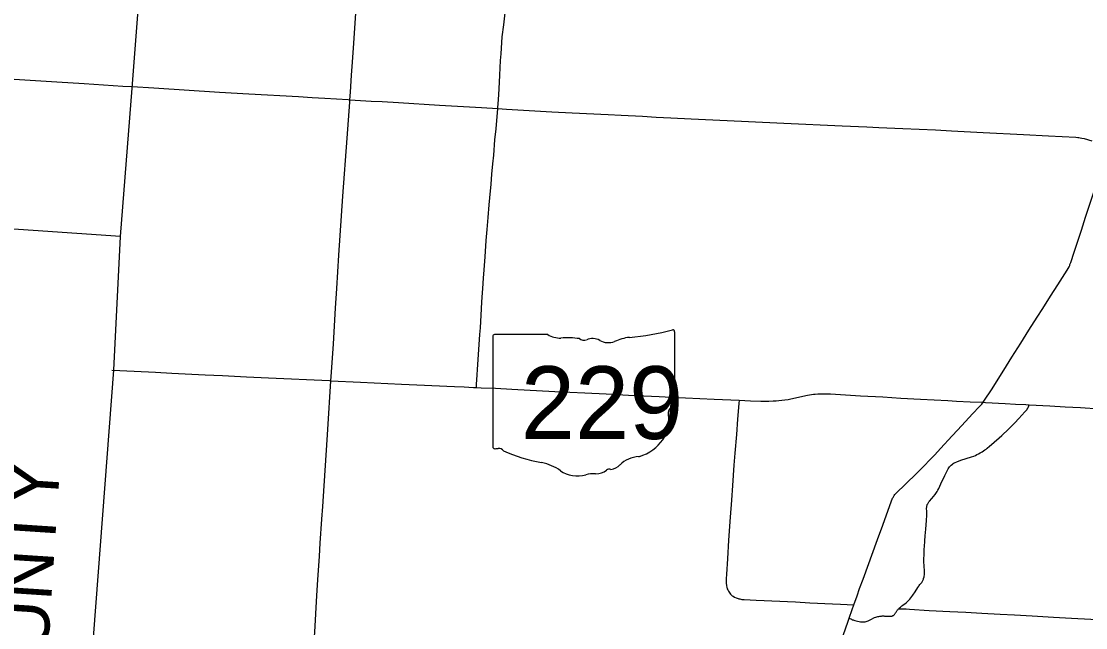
# Model space of a CAD drawing. Extents: x 9078 to 9739, y 4248 to 4966.
# Drawn here: x 9241.2 to 9343, y 4361.8 to 4419.9 of the extents above; entities that cross this region are included whole.
import ezdxf

# ---------------------------------------------------------------- set-up
doc = ezdxf.new("R2010")
doc.units = 0
for name, color, linetype in [('GM_X_Adjacent_County_Text', 7, 'Continuous'), ('GM_X_County', 7, 'Continuous'), ('GM_X_County_Road', 7, 'Continuous'), ('GM_X_State_Route', 7, 'Continuous'), ('GM_X_State_Shield', 7, 'Continuous'), ('GM_X_Township', 7, 'Continuous'), ('GM_X_Township_Road', 7, 'Continuous')]:
    doc.layers.add(name, color=color, linetype=linetype)

msp = doc.modelspace()

# ---------------------------------------------------------------- linework, layer by layer
at = {"layer": 'GM_X_County'}
msp.add_lwpolyline([(9453.47, 4282.4), (9434.47, 4283.67), (9411.76, 4284.99), (9398.2, 4285.94), (9380.71, 4287.14), (9368.35, 4287.79), (9345.5, 4289.28), (9319.89, 4290.94), (9309.14, 4291.62), (9253.07, 4295.4), (9243.76, 4295.73), (9243.93, 4298), (9244.32, 4304.05), (9245.53, 4321.55), (9248.17, 4361.29), (9250.08, 4386.45), (9250.73, 4399.27), (9229.79, 4400.68)], dxfattribs=at)
at = {"layer": 'GM_X_County_Road'}
for points in [[(9333.24, 4383.38), (9333.37, 4383.57), (9334.02, 4384.59), (9335.2, 4386.47), (9335.99, 4387.71), (9336.83, 4389.03), (9337.61, 4390.28), (9338.4, 4391.52), (9338.93, 4392.36), (9339.68, 4393.53), (9340.39, 4394.63), (9341.26, 4396.02), (9341.45, 4396.36), (9341.51, 4396.49), (9341.54, 4396.58), (9341.61, 4396.77), (9341.95, 4397.77), (9342.63, 4399.87), (9343.04, 4401.12), (9343.6, 4402.83), (9344.88, 4406.73), (9345.27, 4407.93)], [(9269.22, 4360.07), (9269.3, 4361.37), (9269.5, 4364.89), (9269.59, 4366.37), (9269.74, 4368.65), (9269.82, 4369.89), (9269.97, 4372.18), (9270.06, 4373.41), (9270.13, 4374.39), (9270.19, 4375.37), (9270.42, 4378.81), (9270.55, 4380.78), (9270.85, 4385.45)], [(9320.87, 4363.98), (9321.17, 4364.85), (9321.42, 4365.54), (9321.76, 4366.46), (9323.12, 4370.25), (9323.63, 4371.63), (9324.46, 4373.95), (9324.53, 4374.11), (9324.57, 4374.2), (9324.62, 4374.28), (9324.68, 4374.38), (9324.73, 4374.46), (9324.8, 4374.55), (9324.89, 4374.65), (9326.83, 4376.54), (9327.52, 4377.24), (9328.21, 4377.95), (9328.6, 4378.36), (9329.16, 4378.96), (9330.27, 4380.17), (9330.77, 4380.71), (9331.56, 4381.55), (9332.22, 4382.27), (9332.9, 4382.99), (9333.1, 4383.2), (9333.24, 4383.38)], [(9320.42, 4362.71), (9320.72, 4363.53), (9320.87, 4363.98)], [(9318.48, 4357.29), (9318.82, 4358.2), (9319.07, 4358.9), (9319.32, 4359.59), (9319.59, 4360.36), (9320.02, 4361.6), (9320.36, 4362.53), (9320.42, 4362.71)]]:
    msp.add_lwpolyline(points, dxfattribs=at)
at = {"layer": 'GM_X_State_Route'}
for points in [[(9249.89, 4386.47), (9250.64, 4386.43), (9254.08, 4386.26), (9255.64, 4386.18), (9258.83, 4386.01), (9260.47, 4385.94), (9262.76, 4385.83), (9264.89, 4385.73), (9270.71, 4385.46), (9270.85, 4385.45), (9273.66, 4385.32), (9277.59, 4385.13), (9279.07, 4385.06), (9282.67, 4384.89), (9283.6, 4384.85)], [(9283.6, 4384.85), (9284.47, 4384.81), (9284.76, 4384.79), (9285.21, 4384.77), (9286.6, 4384.72), (9288.16, 4384.64), (9292.26, 4384.43), (9295.12, 4384.28), (9297.17, 4384.18), (9299.3, 4384.07), (9302.25, 4383.93), (9303.4, 4383.87), (9307.49, 4383.69), (9309.89, 4383.58), (9310.98, 4383.53), (9311.98, 4383.49), (9312.36, 4383.5), (9312.72, 4383.5), (9313.16, 4383.52), (9313.43, 4383.53), (9313.7, 4383.56), (9313.98, 4383.58), (9314.27, 4383.61), (9314.58, 4383.66), (9314.84, 4383.71), (9316.44, 4384.05), (9317.01, 4384.15), (9317.17, 4384.17), (9317.41, 4384.19), (9317.6, 4384.2), (9317.9, 4384.2), (9318.64, 4384.18), (9321.51, 4384.01), (9323.63, 4383.89), (9325.35, 4383.79), (9327.24, 4383.68), (9328.55, 4383.62), (9329.86, 4383.55), (9330.68, 4383.5), (9331.99, 4383.44), (9333.24, 4383.38), (9333.46, 4383.37), (9335.34, 4383.27), (9336.33, 4383.21), (9337.31, 4383.16), (9337.62, 4383.14), (9339.6, 4383.04), (9341.07, 4382.95), (9342.55, 4382.87), (9344.35, 4382.77)]]:
    msp.add_lwpolyline(points, dxfattribs=at)
at = {"layer": 'GM_X_State_Shield'}
for p, q in [((9286.32, 4389.69), (9286.32, 4379.13)), ((9291.59, 4389.87), (9286.5, 4389.87)), ((9303.73, 4384.61), (9303.73, 4390.14)), ((9303.72, 4384.61), (9303.73, 4384.61))]:
    msp.add_line(p, q, dxfattribs=at)
for centre, major_axis, start_param, end_param in [((9297.53, 4404.28), (18.45, 0), 4.814394, 5.042369), ((9303.53, 4390.16), (0.194, 0), 6.141152, 7.989035), ((9286.52, 4389.71), (0.202, 0), 1.712693, 3.28349), ((9292.81, 4391.1), (1.96, 0), 4.042523, 4.731795), ((9293.45, 4383.94), (7.02, 0), 1.404758, 1.657858), ((9295.05, 4389.77), (0.564, 0), 3.836095, 5.185415), ((9295.88, 4388.55), (1.17, 0), 0.950623, 2.079405), ((9297.39, 4390.22), (1.41, 0), 4.081561, 5.145723), ((9299.88, 4386.65), (3.71, 0), 1.699011, 2.107814), ((9303.68, 4384.2), (0.3, 0), 1.883978, 3.671073), ((9303.52, 4384.59), (0.207, 0), 5.05454, 6.418171), ((9301.77, 4383.5), (1.8, 0), 5.934695, 6.695948), ((9298.56, 4381.59), (4.62, 0), 5.101752, 6.440018), ((9304.42, 4382.3), (1.31, 0), 2.387724, 3.262537), ((9286.53, 4379.1), (0.203, 0), 3.00124, 4.508301), ((9286.56, 4380.18), (1.55, 0), 4.665946, 4.897461), ((9286.87, 4378.52), (0.56, 0), 0.519207, 1.627899), ((9293.94, 4388.01), (13.33, 0), 4.195997, 4.488961), ((9300.51, 4376.16), (2.53, 0), 1.647645, 2.488434), ((9289.97, 4374.38), (4.17, 0), 0.823519, 1.323587), ((9297.3, 4378.1), (1.49, 0), 4.937069, 5.64225), ((9294.48, 4378.46), (2.65, 0), 4.026481, 4.996735), ((9296, 4374.81), (2.17, 0), 1.495662, 1.94098), ((9296.2, 4377.67), (1.41, 0), 4.691044, 5.507374), ((9297.47, 4376.65), (0.397, 0), 1.147584, 2.315152)]:
    msp.add_ellipse(centre, major_axis=major_axis, ratio=0.8, start_param=start_param, end_param=end_param, dxfattribs=at)
at = {"layer": 'GM_X_Township'}
msp.add_lwpolyline([(9250.73, 4399.27), (9251.82, 4413.47), (9252.62, 4423.86), (9252.83, 4426.7), (9268.7, 4425.69), (9274.03, 4425.41), (9274.32, 4425.46), (9274.89, 4425.45), (9288.03, 4424.54), (9349.47, 4420.87), (9376.69, 4419.12)], dxfattribs=at)
at = {"layer": 'GM_X_Township_Road'}
for points in [[(9286.81, 4411.51), (9286.82, 4411.61), (9286.87, 4412.34), (9286.93, 4413.4), (9287, 4414.71), (9287.08, 4416.11), (9287.12, 4416.76), (9287.19, 4417.82), (9287.24, 4418.39), (9287.37, 4419.53), (9287.52, 4420.67), (9287.63, 4421.48), (9287.83, 4422.86), (9288.01, 4423.91), (9288.13, 4424.61)], [(9272.82, 4414.69), (9272.87, 4415.55), (9272.98, 4416.86), (9273.03, 4417.76), (9273.25, 4421.11)], [(9231.64, 4414.87), (9232.85, 4414.81), (9233.83, 4414.74), (9234.9, 4414.68), (9236.12, 4414.6), (9237.11, 4414.53), (9240.54, 4414.32), (9244.64, 4414.07), (9247.25, 4413.9), (9250.94, 4413.66), (9251.85, 4413.61)], [(9272.67, 4412.35), (9272.72, 4413.09), (9272.82, 4414.69)], [(9251.85, 4413.61), (9253.9, 4413.48), (9260.2, 4413.09), (9262.98, 4412.93), (9267.73, 4412.65), (9269.04, 4412.57), (9270.27, 4412.5), (9272.48, 4412.36), (9272.67, 4412.35)], [(9270.85, 4385.45), (9270.9, 4386.27), (9271.08, 4388.97), (9271.29, 4392.41), (9271.41, 4394.29), (9271.6, 4397.48), (9271.73, 4399.36), (9271.99, 4403.12), (9272.4, 4408.68), (9272.66, 4412.11), (9272.67, 4412.35)], [(9272.67, 4412.35), (9274.69, 4412.22), (9275.75, 4412.17), (9277.31, 4412.09), (9281.24, 4411.84), (9285.25, 4411.6), (9286.81, 4411.51)], [(9284.76, 4384.79), (9284.76, 4384.94), (9284.77, 4385.11), (9284.79, 4385.52), (9284.89, 4386.99), (9284.96, 4387.97), (9285.09, 4389.86), (9285.14, 4390.51), (9285.22, 4391.74), (9285.28, 4392.97), (9285.32, 4393.46), (9285.38, 4394.28), (9285.45, 4395.26), (9285.51, 4396.08), (9285.57, 4396.9), (9285.6, 4397.31), (9285.71, 4398.86), (9285.79, 4399.92), (9285.88, 4401.07), (9285.99, 4402.3), (9286.04, 4402.95), (9286.16, 4404.26), (9286.25, 4405.24), (9286.34, 4406.22), (9286.42, 4407.04), (9286.54, 4408.51), (9286.64, 4409.57), (9286.81, 4411.51)], [(9286.81, 4411.51), (9287.63, 4411.46), (9291.97, 4411.2), (9293.93, 4411.1), (9297.37, 4410.93), (9298.6, 4410.87), (9300.65, 4410.77), (9301.96, 4410.69), (9303.35, 4410.61), (9305.32, 4410.51), (9307.38, 4410.42), (9310.78, 4410.26), (9314.16, 4410.1), (9319.74, 4409.85), (9322.11, 4409.75), (9323.26, 4409.71), (9325.55, 4409.6), (9328.67, 4409.46), (9330.22, 4409.39), (9333.25, 4409.22), (9337.1, 4409.02), (9339.48, 4408.89), (9342.1, 4408.76), (9342.28, 4408.74), (9342.4, 4408.73), (9342.51, 4408.72), (9342.67, 4408.68), (9342.91, 4408.63), (9343.62, 4408.43)], [(9309.89, 4383.58), (9309.86, 4383.26), (9309.75, 4381.78), (9309.63, 4380.31), (9309.47, 4378.51), (9309.39, 4377.37), (9309.25, 4375.41), (9309.15, 4374.02), (9309.04, 4372.39), (9308.89, 4370.18), (9308.78, 4368.39), (9308.68, 4366.91), (9308.66, 4366.48), (9308.65, 4366.35), (9308.65, 4366.14), (9308.66, 4366.01), (9308.67, 4365.92), (9308.69, 4365.81), (9308.71, 4365.68), (9308.76, 4365.53), (9308.81, 4365.42), (9308.87, 4365.3), (9309.01, 4365.1), (9309.07, 4365.02), (9309.17, 4364.91), (9309.23, 4364.86), (9309.31, 4364.81), (9309.45, 4364.73), (9309.61, 4364.65), (9309.7, 4364.62), (9309.81, 4364.58), (9309.87, 4364.56), (9309.95, 4364.55), (9310.04, 4364.53), (9310.14, 4364.51), (9310.24, 4364.5), (9310.37, 4364.49), (9311.52, 4364.44), (9315.27, 4364.26), (9316.66, 4364.19), (9318.81, 4364.08), (9319.59, 4364.04), (9320.87, 4363.98)], [(9325.17, 4363.61), (9325.2, 4363.64), (9325.22, 4363.66), (9325.24, 4363.69), (9325.33, 4363.76), (9325.4, 4363.82), (9325.47, 4363.88), (9325.54, 4363.94), (9325.87, 4364.19), (9325.99, 4364.3), (9326.11, 4364.42), (9326.22, 4364.53), (9326.33, 4364.66), (9326.41, 4364.77), (9326.52, 4364.92), (9326.73, 4365.24), (9326.98, 4365.64), (9327.07, 4365.77), (9327.11, 4365.83), (9327.18, 4365.92), (9327.24, 4365.99), (9327.29, 4366.05), (9327.36, 4366.14), (9327.43, 4366.25), (9327.47, 4366.32), (9327.5, 4366.37), (9327.52, 4366.43), (9327.54, 4366.5), (9327.58, 4366.66), (9327.61, 4366.91), (9327.62, 4367.03), (9327.63, 4367.18), (9327.62, 4367.29), (9327.59, 4367.67), (9327.58, 4367.74), (9327.58, 4367.81), (9327.57, 4368), (9327.57, 4368.3), (9327.59, 4368.87), (9327.59, 4369.16), (9327.6, 4369.36), (9327.61, 4369.55), (9327.65, 4370.1), (9327.68, 4370.59), (9327.74, 4371.24), (9327.81, 4372.05), (9327.85, 4372.56), (9327.85, 4372.68), (9327.84, 4372.83), (9327.84, 4372.95), (9327.83, 4373.2), (9327.83, 4373.27), (9327.84, 4373.33), (9327.84, 4373.37), (9327.85, 4373.42), (9327.86, 4373.47), (9327.88, 4373.54), (9327.89, 4373.58), (9327.91, 4373.62), (9327.93, 4373.66), (9327.97, 4373.72), (9328.01, 4373.78), (9328.05, 4373.84), (9328.11, 4373.92), (9328.33, 4374.18), (9328.64, 4374.56), (9328.82, 4374.83), (9328.91, 4374.97), (9328.99, 4375.12), (9329.19, 4375.56), (9329.56, 4376.38), (9329.82, 4376.89), (9329.89, 4377.01), (9329.95, 4377.1), (9330.03, 4377.2), (9330.11, 4377.29), (9330.19, 4377.37), (9330.29, 4377.45), (9330.38, 4377.52), (9330.46, 4377.57), (9330.57, 4377.63), (9330.71, 4377.69), (9331.09, 4377.83), (9332.11, 4378.15), (9332.33, 4378.23), (9332.49, 4378.3), (9332.64, 4378.37), (9332.79, 4378.44), (9332.95, 4378.53), (9333.14, 4378.65), (9333.41, 4378.82), (9333.51, 4378.89), (9333.63, 4379), (9333.84, 4379.18), (9334.02, 4379.35), (9335.01, 4380.21), (9335.67, 4380.82), (9336.26, 4381.4), (9336.65, 4381.82), (9337.22, 4382.46), (9337.43, 4382.69), (9337.46, 4382.74), (9337.49, 4382.8), (9337.52, 4382.83), (9337.54, 4382.9), (9337.57, 4382.96), (9337.59, 4383.05), (9337.62, 4383.14)], [(9320.42, 4362.71), (9320.63, 4362.61), (9320.72, 4362.56), (9320.79, 4362.54), (9320.86, 4362.51), (9320.97, 4362.48), (9321.09, 4362.44), (9321.2, 4362.41), (9321.37, 4362.38), (9321.5, 4362.36), (9321.62, 4362.35), (9321.75, 4362.35), (9321.87, 4362.36), (9321.96, 4362.37), (9322.03, 4362.39), (9322.13, 4362.42), (9322.23, 4362.46), (9322.37, 4362.52), (9322.49, 4362.58), (9322.85, 4362.77), (9322.97, 4362.81), (9323.08, 4362.85), (9323.17, 4362.87), (9323.25, 4362.88), (9323.34, 4362.9), (9323.44, 4362.91), (9323.5, 4362.91), (9323.56, 4362.92), (9323.65, 4362.92), (9323.72, 4362.92), (9323.81, 4362.91), (9323.92, 4362.91), (9324.05, 4362.9), (9324.23, 4362.89), (9324.29, 4362.89), (9324.38, 4362.89), (9324.45, 4362.9), (9324.49, 4362.91), (9324.53, 4362.91), (9324.57, 4362.93), (9324.61, 4362.95), (9324.65, 4362.97), (9324.68, 4362.99), (9324.71, 4363.02), (9324.74, 4363.05), (9324.79, 4363.11), (9324.82, 4363.15), (9324.86, 4363.21), (9324.9, 4363.29), (9324.94, 4363.35), (9324.98, 4363.42), (9325.02, 4363.46), (9325.05, 4363.51), (9325.08, 4363.54), (9325.1, 4363.55), (9325.11, 4363.57), (9325.14, 4363.59), (9325.17, 4363.61)], [(9325.17, 4363.61), (9325.19, 4363.61), (9325.24, 4363.62), (9325.29, 4363.62), (9325.32, 4363.62), (9325.37, 4363.62), (9325.61, 4363.61), (9325.87, 4363.6), (9326.2, 4363.58), (9328.07, 4363.46), (9330.04, 4363.36), (9331.59, 4363.28), (9333.12, 4363.2), (9334.85, 4363.1), (9336.22, 4363.02), (9337.91, 4362.92), (9339.96, 4362.81), (9341.68, 4362.72), (9344.79, 4362.56), (9346.59, 4362.46), (9350.69, 4362.25)]]:
    msp.add_lwpolyline(points, dxfattribs=at)

# ---------------------------------------------------------------- texts
at = {"layer": 'GM_X_Adjacent_County_Text'}
msp.add_text('DELAWARE COUNTY', height=5, rotation=86.2231, dxfattribs=at).set_placement((9240.51, 4310.18))
at = {"layer": 'GM_X_State_Shield'}
msp.add_text('229', height=6.961, dxfattribs=at).set_placement((9289.02, 4379.87))

doc.saveas('drawing.dxf')
